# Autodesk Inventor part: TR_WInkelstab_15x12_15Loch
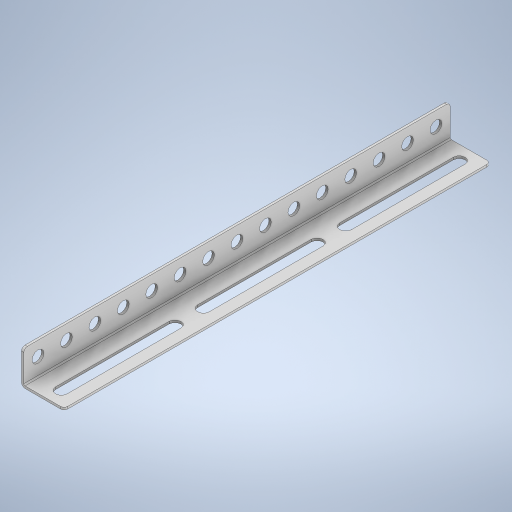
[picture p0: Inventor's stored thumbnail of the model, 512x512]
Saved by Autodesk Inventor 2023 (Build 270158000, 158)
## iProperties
Created: 2023-11
Part Number: TR_WInkelstab_15x12_15Loch
Material: Generisch
Document SubType Name: Modeling
Designer: Administrator
Density: 1 g/cm^3
Appearance: Vorgabe
Author: Administrator
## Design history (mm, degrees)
sketch "Skizze1"
  geometry: L1 (0, 12)-(0, 1.25); L2 (1.25, 0)-(15, 0); L3 (15, 0)-(15, 0.8); L4 (15, 0.8)-(1.25, 0.8); L5 (0.8, 1.25)-(0.8, 12); L6 (0.8, 12)-(0, 12); A1 r 1.25 centre (1.25, 1.25) between (0, 1.25) and (1.25, 0); A2 r 0.45 centre (1.25, 1.25) between (0.8, 1.25) and (1.25, 0.8); 1 further point
  constraints: 12 end point, 5 perpendicular, 4 point on circle, 4 tangent, 2 centre point, 2 point on line, 1 coincident, 1 vertical
  dimensions: "d0" = 1.25 radius of A1; "d2" = 0.8 distance of L5.end L1.start (= Dicke); "d3" = 12 distance of point (0, 0) L1.start; "d4" = 15 distance of point (0, 0) L2.end
extrude "Extrusion1" new body sketch "Skizze1" stored distance "d5" = 150 (computed from Lochzahl, Einheitsmaß); taper "d6" = 0 deg
sketch "Skizze2"
  geometry: L1 (7.75, 5)-(7.75, 45); L2 (9.825, 5)-(9.825, 45); L3 (5.675, 45)-(5.675, 5); L4 (13.75, 150)-(13.75, 0) reference; L5 (13.75, 0)-(0, 0) reference; A1 r 2.075 centre (7.75, 5) between (5.675, 5) and (9.825, 5); A2 r 2.075 centre (7.75, 45) between (9.825, 45) and (5.675, 45); 3 further points
  constraints: 8 end point, 4 point on circle, 4 tangent, 2 centre point, 2 midpoint, 1 parallel, 1 vertical
  dimensions: "d8" = 4.15 diameter of A2 (= 2 x Radius); "d9" = 40 distance of L1.start L1.end (= Langloch); "d10" = 6 distance from line of L4 L1.start; "d11" = 5 vertical distance of point (6.875, 0) L1.start (= 0.5 x Einheitsmaß)
extrude "Extrusion2" cut sketch "Skizze2" extent not by distance; stored distance "d12" = 0; taper "d13" = 0 deg
sketch "Skizze3"
  geometry: L1 (0, 10.75)-(150, 10.75) reference; L2 (0, 0)-(0, 10.75) reference; C1 r 2.075 at (5, 5.75); 1 further point
  constraints: 1 centre point
  dimensions: "d14" = 4.15 diameter of C1 (= 2 x Radius); "d15" = 5 distance from line of C1.centre L1 (= 0.5 x Einheitsmaß); "d16" = 5 distance from line of C1.centre L2 (= 0.5 x Einheitsmaß)
extrude "Extrusion3" cut sketch "Skizze3" extent not by distance; stored distance "d17" = 0; taper "d18" = 0 deg
pattern_linear "Rechteckige Anordnung1" dims "d21" = 10 (= Einheitsmaß)
fillet "Rundung1" dims "d22" = 1.25
pattern_linear "Rechteckige Anordnung2" dims "d25" = 50
node "Volumenkörper1"
other parameters: "Einheitsmaß" = 10 [user parameter; used in 5 equation terms], "Radius" = 2.075 [user parameter; used in 2 equation terms], "Fasen" = 0.5 [user parameter], "Dicke" = 0.8 [user parameter; used in 1 equation term], "Breitloch" = 2 [user parameter], "Langloch" = 40 [user parameter; used in 1 equation term], "AchteckUmkreis" = 6 [user parameter], "DAchsAufnahme" = 4.1 [user parameter], "AchsDurchmesser" = 4 [user parameter], "AchsFase" = 0.5 [user parameter]
